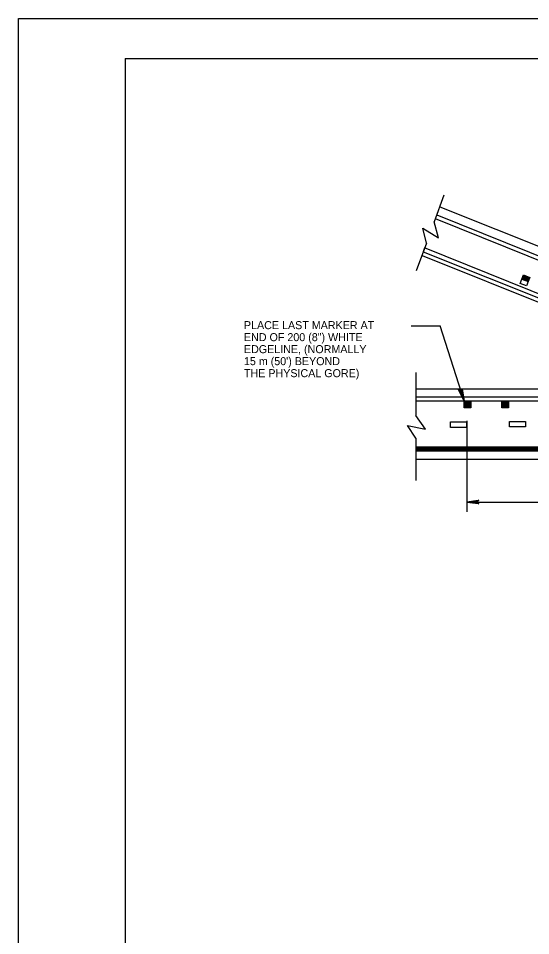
# Model space of a CAD drawing. Extents: x 639362 to 641108, y 298458 to 299646.
# Drawn here: x 639362.3 to 639554.2, y 299301.7 to 299645.6 of the extents above; entities that cross this region are included whole.
import ezdxf

# ---------------------------------------------------------------- set-up
doc = ezdxf.new("R2010")
doc.units = 0
for name, color, linetype in [('1', 7, 'Continuous'), ('2', 7, 'Continuous'), ('PLT-BNDY', 7, 'Continuous')]:
    doc.layers.add(name, color=color, linetype=linetype)

msp = doc.modelspace()

# ---------------------------------------------------------------- linework, layer by layer
at = {"layer": '1'}
for q in [(640188.31, 299630.63), (639402.31, 299066.63)]:
    msp.add_line((639402.31, 299630.63), q, dxfattribs=at)
at = {"layer": '2'}
for p, q in [((639521.73, 299579.34), (639518.1, 299569.36)), ((639520.27, 299575.01), (639582.89, 299549.8)), ((639519.04, 299571.94), (639581.66, 299546.74)), ((639519.78, 299563.31), (639518.1, 299569.36)), ((639518.53, 299570.53), (639581.1, 299545.35)), ((639515.2, 299561.39), (639513.85, 299566.96)), ((639513.85, 299566.96), (639519.78, 299563.31)), ((639515.2, 299561.39), (639511.41, 299550.98)), ((639514.53, 299559.55), (639514.01, 299558.14)), ((639514.01, 299558.14), (639601.34, 299522.99)), ((639601.87, 299524.4), (639514.53, 299559.55)), ((639513.56, 299556.71), (639600.9, 299521.56)), ((639551, 299547.83), (639551.62, 299549.41)), ((639553.32, 299546.91), (639551, 299547.83)), ((639551.2, 299547.83), (639551.77, 299549.26)), ((639553.18, 299547.05), (639551.2, 299547.83)), ((639551.41, 299547.87), (639551.89, 299549.09)), ((639553.06, 299547.22), (639551.41, 299547.87)), ((639551.62, 299549.41), (639553.95, 299548.49)), ((639551.62, 299547.91), (639552.01, 299548.92)), ((639552.94, 299547.39), (639551.62, 299547.91)), ((639551.77, 299549.26), (639553.74, 299548.48)), ((639551.82, 299547.96), (639552.14, 299548.75)), ((639552.81, 299547.56), (639551.82, 299547.96)), ((639551.89, 299549.09), (639553.54, 299548.43)), ((639552.01, 299548.92), (639553.33, 299548.39)), ((639552.03, 299548), (639552.26, 299548.58)), ((639552.69, 299547.73), (639552.03, 299548)), ((639552.14, 299548.75), (639553.13, 299548.35)), ((639552.24, 299548.04), (639552.38, 299548.41)), ((639552.57, 299547.9), (639552.24, 299548.04)), ((639552.26, 299548.58), (639552.92, 299548.31)), ((639552.38, 299548.41), (639552.71, 299548.28)), ((639552.5, 299548.24), (639552.44, 299548.08)), ((639552.71, 299548.28), (639552.57, 299547.9)), ((639552.92, 299548.31), (639552.69, 299547.73)), ((639553.13, 299548.35), (639552.81, 299547.56)), ((639553.33, 299548.39), (639552.94, 299547.39)), ((639553.54, 299548.43), (639553.06, 299547.22)), ((639553.74, 299548.48), (639553.18, 299547.05)), ((639553.95, 299548.49), (639553.32, 299546.91)), ((639509.45, 299530.37), (639520.32, 299530.37)), ((639529.3, 299502.21), (639520.32, 299530.37)), ((639511.24, 299512.9), (639511.24, 299496.69)), ((639511.24, 299506.72), (639644.37, 299506.72)), ((639511.24, 299503.69), (639660.34, 299503.69)), ((639511.24, 299502.19), (639736.84, 299502.19)), ((639529.3, 299502.21), (639531.79, 299502.21)), ((639529.3, 299499.56), (639529.3, 299502.21)), ((639529.48, 299502.08), (639531.61, 299502.08)), ((639529.48, 299499.68), (639529.48, 299502.08)), ((639529.66, 299501.9), (639531.44, 299501.9)), ((639529.66, 299499.86), (639529.66, 299501.9)), ((639531.44, 299501.9), (639531.44, 299499.86)), ((639531.61, 299502.08), (639531.61, 299499.68)), ((639531.79, 299502.21), (639531.79, 299499.56)), ((639543.47, 299502.18), (639545.97, 299502.18)), ((639543.47, 299499.53), (639543.47, 299502.18)), ((639543.66, 299502.05), (639545.79, 299502.05)), ((639543.66, 299499.65), (639543.66, 299502.05)), ((639543.84, 299501.87), (639545.61, 299501.87)), ((639543.84, 299499.83), (639543.84, 299501.87)), ((639545.61, 299501.87), (639545.61, 299499.83)), ((639545.79, 299502.05), (639545.79, 299499.65)), ((639545.97, 299502.18), (639545.97, 299499.53)), ((639531.79, 299499.56), (639529.3, 299499.56)), ((639531.61, 299499.68), (639529.48, 299499.68)), ((639531.44, 299499.86), (639529.66, 299499.86)), ((639529.84, 299501.72), (639531.26, 299501.72)), ((639529.84, 299500.04), (639529.84, 299501.72)), ((639531.26, 299500.04), (639529.84, 299500.04)), ((639530.02, 299501.54), (639531.08, 299501.54)), ((639530.02, 299500.22), (639530.02, 299501.54)), ((639531.08, 299500.22), (639530.02, 299500.22)), ((639530.19, 299500.39), (639530.19, 299501.37)), ((639530.19, 299501.37), (639530.9, 299501.37)), ((639530.9, 299500.39), (639530.19, 299500.39)), ((639530.37, 299501.19), (639530.72, 299501.19)), ((639530.37, 299500.57), (639530.37, 299501.19)), ((639530.72, 299500.57), (639530.37, 299500.57)), ((639530.55, 299501.01), (639530.55, 299500.75)), ((639530.72, 299501.19), (639530.72, 299500.57)), ((639530.9, 299501.37), (639530.9, 299500.39)), ((639531.08, 299501.54), (639531.08, 299500.22)), ((639531.26, 299501.72), (639531.26, 299500.04)), ((639545.97, 299499.53), (639543.47, 299499.53)), ((639545.79, 299499.65), (639543.66, 299499.65)), ((639545.61, 299499.83), (639543.84, 299499.83)), ((639544.01, 299501.69), (639545.43, 299501.69)), ((639544.01, 299500.01), (639544.01, 299501.69)), ((639545.43, 299500.01), (639544.01, 299500.01)), ((639544.19, 299501.52), (639545.26, 299501.52)), ((639544.19, 299500.19), (639544.19, 299501.52)), ((639545.26, 299500.19), (639544.19, 299500.19)), ((639544.37, 299500.36), (639544.37, 299501.34)), ((639544.37, 299501.34), (639545.08, 299501.34)), ((639545.08, 299500.36), (639544.37, 299500.36)), ((639544.55, 299501.16), (639544.9, 299501.16)), ((639544.55, 299500.54), (639544.55, 299501.16)), ((639544.9, 299500.54), (639544.55, 299500.54)), ((639544.72, 299500.98), (639544.72, 299500.72)), ((639544.9, 299501.16), (639544.9, 299500.54)), ((639545.08, 299501.34), (639545.08, 299500.36)), ((639545.26, 299501.52), (639545.26, 299500.19)), ((639545.43, 299501.69), (639545.43, 299500.01)), ((639514.89, 299491.58), (639511.24, 299496.69)), ((639511.24, 299488.21), (639508.06, 299492.98)), ((639508.06, 299492.98), (639514.89, 299491.58)), ((639524.18, 299492.28), (639524.18, 299494.35)), ((639524.18, 299494.35), (639530.19, 299494.35)), ((639530.19, 299492.28), (639524.18, 299492.28)), ((639530.19, 299494.35), (639530.19, 299492.28)), ((639530.33, 299494.77), (639530.33, 299460.62)), ((639546.37, 299492.47), (639546.37, 299494.53)), ((639546.37, 299494.53), (639552.38, 299494.53)), ((639552.38, 299492.47), (639546.37, 299492.47)), ((639552.38, 299494.53), (639552.38, 299492.47)), ((639511.24, 299488.21), (639511.24, 299472.39)), ((639511.24, 299484.99), (639812.25, 299484.99)), ((639511.24, 299484.84), (639812.25, 299484.84)), ((639511.24, 299484.69), (639812.25, 299484.69)), ((639511.24, 299484.54), (639812.25, 299484.54)), ((639511.24, 299484.39), (639812.25, 299484.39)), ((639511.24, 299484.24), (639812.25, 299484.24)), ((639511.24, 299484.09), (639812.25, 299484.09)), ((639511.24, 299483.94), (639812.25, 299483.94)), ((639511.24, 299483.79), (639812.25, 299483.79)), ((639511.24, 299483.64), (639812.25, 299483.64)), ((639511.24, 299483.49), (639812.25, 299483.49)), ((639511.24, 299480.35), (639812.25, 299480.35)), ((639530.33, 299464.27), (639733.68, 299464.27))]:
    msp.add_line(p, q, dxfattribs=at)
msp.add_lwpolyline([(639551, 299547.83), (639553.32, 299546.91), (639552.7, 299545.33), (639550.38, 299546.25)], close=True, dxfattribs=at)
for points in [[(639528.47, 299506.48), (639528.23, 299506.23), (639529.3, 299502.21), (639528.47, 299506.48), (639528.59, 299506.75), (639529.3, 299502.21), (639527.82, 299506.09), (639527.47, 299506.14), (639529.3, 299502.21), (639527.21, 299506.3), (639527.47, 299506.14)], [(639534.64, 299463.73), (639534.48, 299464.04), (639530.33, 299464.27), (639534.64, 299463.73), (639534.86, 299463.54), (639530.33, 299464.27), (639534.48, 299464.48), (639534.63, 299464.79), (639530.33, 299464.27), (639534.86, 299464.99), (639534.63, 299464.79)]]:
    msp.add_lwpolyline(points, dxfattribs=at)
at = {"layer": 'PLT-BNDY'}
msp.add_lwpolyline([(639362.31, 299645.63), (640203.31, 299645.63), (640203.31, 299051.63), (639362.31, 299051.63)], close=True, dxfattribs=at)

# ---------------------------------------------------------------- texts
at = {"layer": '2'}
for s, p in [('PLACE LAST MARKER AT', (639446.83, 299529.09)), ('END OF 200 (8") WHITE', (639446.83, 299524.59)), ('EDGELINE, (NORMALLY ', (639446.83, 299520.09)), ("15 m (50') BEYOND", (639446.83, 299515.59)), ('THE PHYSICAL GORE)', (639446.83, 299511.09))]:
    msp.add_text(s, height=3, dxfattribs=at).set_placement(p)

doc.saveas('drawing.dxf')
